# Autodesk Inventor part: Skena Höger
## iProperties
Author: Tobben
Created: 2001-12
Part Number: Skena Höger
Material: Steel, Mild
Document SubType Name: Modeling
Designer: Tobben
Control State: 0
Master: False
Checked Out: False
PropertySet Name: Design Tracking Control
Shininess: 64.0
Angle Display Precision: 2
Document Length Units: 11269
Document Angle Units: 11283
Document Time Units: 11279
Document Mass Units: 11290
Document Length Units Precision: 3
Document Angle Units Precision: 2
Compacted: False
PropertySet Name: _Private Model Information
Density: 0.0
Volumn: 0.0
Area: 0.0
PropertySet Name: Model Information
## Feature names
1. Derived Body1 [Tagging]
